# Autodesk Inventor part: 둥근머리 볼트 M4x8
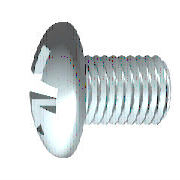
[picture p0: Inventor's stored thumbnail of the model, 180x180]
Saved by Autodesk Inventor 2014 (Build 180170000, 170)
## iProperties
Created: 2012-02
Part Number: 둥근머리 볼트 M4x8
Material: 강철, 연강
Description: 십자 오목 머리 나사
Document SubType Name: Modeling
Standard: KS B 1023
Designer: mduedu
Standards Organization: KS
Language: ko-KR
Size Designation: A  M 4 x 8 - H
Categories: <MemberInstance><Categories><Category DisplayName="조임쇠" InternalName="e4da775c-781d-43d5-af7c-5136215cf5a6" Mnemonic="FSTN"><Category DisplayName="볼트" InternalN
Density: 7.86 g/cm^3
Appearance: 노란색
Mass: 1.6193 g
Surface Area: 2.62082 cm^2
Volume: 0.206017 cm^3
IsCustomPart: 1
Author: mduedu
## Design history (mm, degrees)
workplane "Work Plane3"
sketch "스케치2"
  geometry: L1 (-5.374, 0)-(5.374, 0) reference; L2 (0, -5.374)-(0, 5.374) reference; L3 (0, 2.3)-(0, 0); L4 (0, 0)-(2.3, 0); L5 (0, 0)-(2.714, 2.714); L6 (0.311, 2.279)-(0.392, 0.703); L7 (2.279, 0.311)-(0.703, 0.392); L8 (0.311, -2.279)-(0.392, -0.703); L9 (2.279, -0.311)-(0.703, -0.392); L10 (-0.311, 2.279)-(-0.392, 0.703); L11 (-2.279, 0.311)-(-0.703, 0.392); L12 (-2.279, -0.311)-(-0.703, -0.392); L13 (-0.311, -2.279)-(-0.392, -0.703); A1 r 0.69 centre (0, 0) between (0.69, 0) and (0, 0.69); A2 r 2.3 centre (0, 0) between (2.3, 0) and (2.279, 0.311); A3 r 2.3 centre (0, 0) between (0.311, 2.279) and (0, 2.3); A4 r 2.3 centre (0, 0) between (2.279, 0.311) and (0.311, 2.279); A5 r 2.3 centre (0, 0) between (0, -2.3) and (0.311, -2.279); A6 r 2.3 centre (0, 0) between (0.311, -2.279) and (2.279, -0.311); A7 r 2.3 centre (0, 0) between (2.279, -0.311) and (2.3, 0); A8 r 2.3 centre (0, 0) between (-2.279, 0.311) and (-2.3, 0); A9 r 2.3 centre (0, 0) between (-0.311, 2.279) and (-2.279, 0.311); A10 r 2.3 centre (0, 0) between (0, 2.3) and (-0.311, 2.279); A11 r 2.3 centre (0, 0) between (-2.3, 0) and (-2.279, -0.311); A12 r 2.3 centre (0, 0) between (-2.279, -0.311) and (-0.311, -2.279); A13 r 2.3 centre (0, 0) between (-0.311, -2.279) and (0, -2.3); A14 r 0.805 centre (0, 0) between (0.805, 0) and (0, 0.805); A15 r 0.328 centre (0.72, 0.72) between (0.392, 0.703) and (0.703, 0.392); A16 r 0.328 centre (0.72, -0.72) between (0.703, -0.392) and (0.392, -0.703); A17 r 0.328 centre (-0.72, 0.72) between (-0.703, 0.392) and (-0.392, 0.703); A18 r 0.328 centre (-0.72, -0.72) between (-0.392, -0.703) and (-0.703, -0.392); 1 further point
  constraints: 38 point on circle, 22 end point, 19 symmetric about line, 18 centre point, 4 coincident, 3 collinear, 3 point on line, 3 tangent, 1 perpendicular, 21 other
  dimensions: "d4" = 45 deg angle of L5 L4; "d5" = 1.38 diameter of A1 (= 0.3 x SDM); "d6" = 4.6 diameter of A4 (= SDM); "d7" = 0.3115 distance from line of L6.start L3 (= 0.5 x SBR); "d14" = 1.61 diameter of A14 (= 0.35 x SDM)
extrude "슬롯" join sketch "스케치2" taper "d15" = 5 deg; stored distance "d54" = 10
revolve "절단부" stored, may be unused: angle "d56" = 90 deg
revolve "본체" stored, may be unused: angle "d18" = 90 deg
workplane "Work Plane1"
body "Solid1"
sketch "스케치1"
  geometry: L1 (8, 0)-(8, 2); L2 (8, 2)-(1.4, 2); L3 (3.962, 5.08)-(3.962, 5.08); L4 (-3.1, 0)-(-3.1, 3.729); L5 (-2.744, 2.122)-(-1.498, 1.501); L6 (-1.498, 1.501)-(-0.7, 0); L7 (-0.7, 0)-(8, 0); L8 (-5.687, 0)-(10.281, 0) reference; L9 (0, -1.016)-(0, 6.096) reference; L10 (-2.744, 2.122)-(-3.1, 2.3); L11 (-1.846, 3.839)-(-3.1, 3.729); L12 (-1.846, 3.839)-(0, 4); L13 (0, 4)-(0, 1.785); L14 (0, 1.785)-(0.971, 1.785); L15 (0.971, 1.785)-(1.4, 2); L16 (1.4, 2)-(0, 2); A1 r 6.5 centre (3.4, 0) between (-1.846, 3.839) and (-3.1, 0)
  constraints: 28 end point, 5 point on line, 4 collinear, 4 point on circle, 3 parallel, 2 perpendicular, 1 centre point, 1 horizontal, 1 tangent
  dimensions: "d1" = 4 diameter of L2 L7 (= GD); "d2" = 2.4 distance from line of L6.end L4 (= STI); "d11" = 4.6 diameter of L10.end L7 (= SDM); "d12" = 62 deg angle of L6 L7; "d13" = 26.5 deg angle of L5 L7; "d17" = 8 diameter of L12.end L7 (= KOD); "d19" = 5 deg angle of L12 L7 (= KEWI); "d20" = 3.1 distance between parallel lines of L4 L13 (= KOH); "d21" = 6.5 radius of A1 (= KR); "d23" = 3.5705 diameter of L14 L7 (= BDM); "d24" = 6.6 distance of L1.end L2.end (= GEL); "d25" = 0.42941 horizontal distance of L14.end L2.end (= GAL); "d28" = 8 distance between parallel lines of L1 L13 (= NLG)
fillet "모깎기1" dims "d29" = 1.6 (= RR)
fillet "모깎기2" dims "d16" = 0.1246 (= 0.2 x SBR)
feature "스레드" dims "d8" = 6.6 (= GEL), "d9" = 0
chamfer "모따기1" distance "d26" = 0.42941 (= -0.5 x SPD + 0.5 x GD); stored, may be unused: second distance "d27" = 0.42952 (computed from GUL), angle "d78" = 45 deg
other parameters: "GD" = 4 (= NND) [user parameter; used in 2 equation terms], "NLG" = 8 [user parameter; used in 1 equation term], "GEL" = 6.6 [user parameter; used in 2 equation terms], "KOD" = 8 [user parameter; used in 1 equation term], "KOH" = 3.1 [user parameter; used in 2 equation terms], "SDM" = 4.6 [user parameter; used in 4 equation terms], "STI" = 2.4 [user parameter; used in 1 equation term], "SBR" = 0.623 [user parameter; used in 2 equation terms], "GAL" = 0.42941 (= 0.61345 x PTC) [user parameter; used in 1 equation term], "SPD" = 3.14117 (= NND - 1.2269 x PTC) [user parameter; used in 1 equation term], "KEWI" = 5 deg [user parameter; used in 1 equation term], "d3" = -3.1 (= -KOH), "d10" = 0, "KR" = 6.5 [user parameter; used in 1 equation term], "BDM" = 3.5705 [user parameter; used in 1 equation term], "GUL" = 0.42941 (= 0.61345 x PTC) [user parameter; used in 1 equation term], "RR" = 1.6 [user parameter; used in 1 equation term], "d79" = 0, "d80" = 0, "PTC" = 0.7 [user parameter; used in 5 equation terms], "THREADDIA" = 4 [user parameter; used in 1 equation term], "TOA" = 30 deg [user parameter], "TPU" = 14.28571 (computed from PTC) [user parameter], "NND" = 4 [user parameter; used in 2 equation terms], "GD1" = 3.14117 (= THREADDIA - 1.2269 x PTC) [user parameter]
